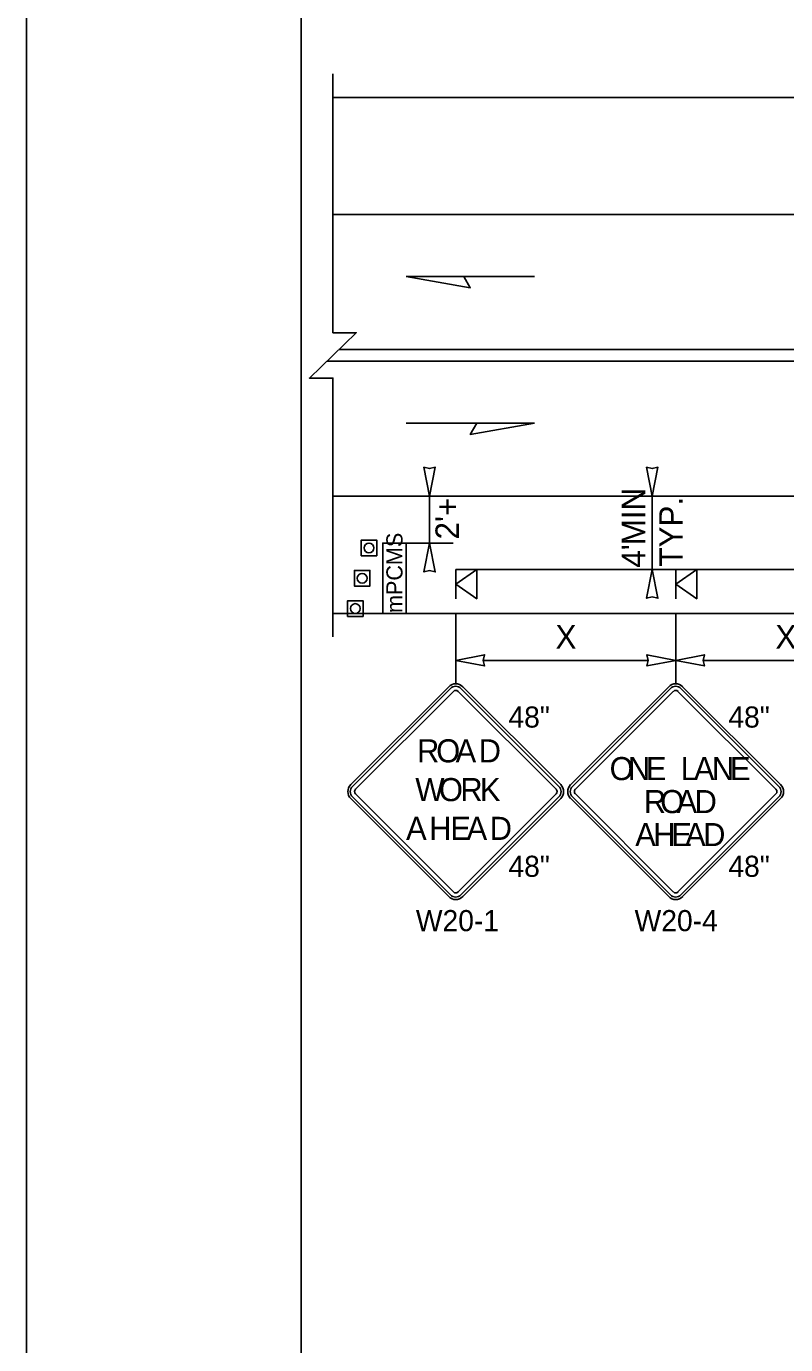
# Model space of a CAD drawing. Extents: x 99999.1 to 100095.7, y 99995 to 100010.7.
# Drawn here: x 100039.062 to 100041.652, y 100003.239 to 100007.734 of the extents above; entities that cross this region are included whole.
import ezdxf

# ---------------------------------------------------------------- set-up
doc = ezdxf.new("R2010")
doc.units = 0
for name, color, linetype in [('RD_ED_ShoulderPavedEdge', 7, 'Continuous'), ('RD_MK_LineDblYellowCenter', 7, 'Continuous'), ('RD_MK_LineEdgeWhite', 7, 'Continuous'), ('SH_GI_PlotLimits', 7, 'Continuous'), ('SH_GI_SheetBorder', 7, 'Continuous'), ('TR_SN_ConstructionSigns', 7, 'Continuous'), ('TR_WZ_PCMS', 7, 'Continuous'), ('TR_WZ_PortableSignMountBlk-Org', 7, 'Continuous'), ('TR_WZ_TrafficCone', 7, 'Continuous'), ('TR_WZ_WorkZoneDetails', 7, 'Continuous'), ('TR_WZ_WorkZoneTextCurrent', 7, 'Continuous')]:
    doc.layers.add(name, color=color, linetype=linetype)

msp = doc.modelspace()

# ---------------------------------------------------------------- linework, layer by layer
at = {"layer": 'RD_ED_ShoulderPavedEdge'}
for p, q in [((100040.1076, 100007.4923), (100055.6424, 100007.4923)), ((100040.1076, 100005.7323), (100055.6424, 100005.7323))]:
    msp.add_line(p, q, dxfattribs=at)
at = {"layer": 'RD_MK_LineDblYellowCenter'}
for p, q in [((100040.1282, 100006.6323), (100043.4767, 100006.6323)), ((100040.0869, 100006.5923), (100043.4767, 100006.5923))]:
    msp.add_line(p, q, dxfattribs=at)
at = {"layer": 'RD_MK_LineEdgeWhite'}
for p, q in [((100040.1076, 100007.0923), (100055.6424, 100007.0923)), ((100040.1076, 100006.1323), (100055.6424, 100006.1323))]:
    msp.add_line(p, q, dxfattribs=at)
at = {"layer": 'SH_GI_PlotLimits'}
msp.add_lwpolyline([(100039.0625, 99999.6875), (100056.0625, 99999.6875), (100056.0625, 100010.6875), (100039.0625, 100010.6875)], close=True, dxfattribs=at)
at = {"layer": 'SH_GI_SheetBorder'}
msp.add_line((100040, 100010.375), (100040, 100000), dxfattribs=at)
at = {"layer": 'TR_SN_ConstructionSigns'}
for p, q in [((100040.5028, 100005.4824), (100040.1687, 100005.1483)), ((100040.8846, 100005.1483), (100040.5505, 100005.4824)), ((100041.2528, 100005.4824), (100040.9187, 100005.1483)), ((100041.6346, 100005.1483), (100041.3005, 100005.4824)), ((100040.5088, 100005.4765), (100040.1746, 100005.1424)), ((100040.1846, 100005.1324), (100040.5187, 100005.4665)), ((100040.5346, 100005.4665), (100040.8687, 100005.1324)), ((100040.8787, 100005.1424), (100040.5445, 100005.4765)), ((100041.2588, 100005.4765), (100040.9246, 100005.1424)), ((100040.9346, 100005.1324), (100041.2687, 100005.4665)), ((100041.2846, 100005.4665), (100041.6187, 100005.1324)), ((100041.6287, 100005.1424), (100041.2945, 100005.4765)), ((100040.1687, 100005.1006), (100040.5028, 100004.7665)), ((100040.1746, 100005.1066), (100040.5088, 100004.7725)), ((100040.5187, 100004.7824), (100040.1846, 100005.1165)), ((100040.8687, 100005.1165), (100040.5346, 100004.7824)), ((100040.5445, 100004.7725), (100040.8787, 100005.1066)), ((100040.5505, 100004.7665), (100040.8846, 100005.1006)), ((100040.9187, 100005.1006), (100041.2528, 100004.7665)), ((100040.9246, 100005.1066), (100041.2588, 100004.7725)), ((100041.2687, 100004.7824), (100040.9346, 100005.1165)), ((100041.6187, 100005.1165), (100041.2846, 100004.7824)), ((100041.2945, 100004.7725), (100041.6287, 100005.1066)), ((100041.3005, 100004.7665), (100041.6346, 100005.1006))]:
    msp.add_line(p, q, dxfattribs=at)
for centre, radius, start, end in [((100040.5267, 100005.4586), 0.0338, 45, 135), ((100040.5267, 100005.4586), 0.0253, 45, 135), ((100041.2767, 100005.4586), 0.0338, 45, 135), ((100041.2767, 100005.4586), 0.0253, 45, 135), ((100040.5267, 100005.4586), 0.0113, 45, 135), ((100041.2767, 100005.4586), 0.0113, 45, 135), ((100040.1925, 100005.1245), 0.0338, 135, 225), ((100040.1925, 100005.1245), 0.0253, 135, 225), ((100040.1925, 100005.1245), 0.0113, 135, 225), ((100040.8608, 100005.1245), 0.0113, 315, 45), ((100040.8608, 100005.1245), 0.0253, 315, 45), ((100040.8608, 100005.1245), 0.0338, 315, 45), ((100040.9425, 100005.1245), 0.0338, 135, 225), ((100040.9425, 100005.1245), 0.0253, 135, 225), ((100040.9425, 100005.1245), 0.0113, 135, 225), ((100041.6108, 100005.1245), 0.0113, 315, 45), ((100041.6108, 100005.1245), 0.0253, 315, 45), ((100041.6108, 100005.1245), 0.0338, 315, 45), ((100040.5267, 100004.7904), 0.0338, 225, 315), ((100040.5267, 100004.7904), 0.0253, 225, 315), ((100040.5267, 100004.7904), 0.0113, 225, 315), ((100041.2767, 100004.7904), 0.0338, 225, 315), ((100041.2767, 100004.7904), 0.0253, 225, 315), ((100041.2767, 100004.7904), 0.0113, 225, 315)]:
    msp.add_arc(centre, radius, start, end, dxfattribs=at)
at = {"layer": 'TR_WZ_PCMS'}
msp.add_lwpolyline([(100040.3576, 100005.7323), (100040.3576, 100005.9723), (100040.2776, 100005.9723), (100040.2776, 100005.7323)], close=True, dxfattribs=at)
msp.add_lwpolyline([(100040.3576, 100005.7323), (100040.3576, 100005.9723), (100040.2776, 100005.9723), (100040.2776, 100005.7323), (100040.3576, 100005.7323)], dxfattribs=at)
at = {"layer": 'TR_WZ_PortableSignMountBlk-Org'}
for p, q in [((100040.5267, 100005.7824), (100040.5267, 100005.8824)), ((100041.2767, 100005.7824), (100041.2767, 100005.8824))]:
    msp.add_line(p, q, dxfattribs=at)
for points in [[(100040.5267, 100005.8323), (100040.5985, 100005.8824), (100040.5985, 100005.7824)], [(100041.2767, 100005.8323), (100041.3485, 100005.8824), (100041.3485, 100005.7824)]]:
    msp.add_lwpolyline(points, close=True, dxfattribs=at)
at = {"layer": 'TR_WZ_TrafficCone'}
for points in [[(100040.2042, 100005.9823), (100040.2576, 100005.9823), (100040.2576, 100005.929), (100040.2042, 100005.929), (100040.2042, 100005.9823)], [(100040.2042, 100005.929), (100040.2576, 100005.929), (100040.2576, 100005.9823), (100040.2042, 100005.9823), (100040.2042, 100005.929)], [(100040.1809, 100005.879), (100040.2342, 100005.879), (100040.2342, 100005.8257), (100040.1809, 100005.8257), (100040.1809, 100005.879)], [(100040.1809, 100005.8257), (100040.2342, 100005.8257), (100040.2342, 100005.879), (100040.1809, 100005.879), (100040.1809, 100005.8257)], [(100040.1576, 100005.7757), (100040.2109, 100005.7757), (100040.2109, 100005.7223), (100040.1576, 100005.7223), (100040.1576, 100005.7757)], [(100040.1576, 100005.7223), (100040.2109, 100005.7223), (100040.2109, 100005.7757), (100040.1576, 100005.7757), (100040.1576, 100005.7223)]]:
    msp.add_lwpolyline(points, dxfattribs=at)
for centre in [(100040.2309, 100005.9557), (100040.2076, 100005.8523), (100040.1842, 100005.749)]:
    msp.add_circle(centre, 0.0167, dxfattribs=at)
at = {"layer": 'TR_WZ_WorkZoneDetails'}
for p, q in [((100040.5541, 100006.8816), (100040.7952, 100006.8816)), ((100040.5987, 100006.3816), (100040.3576, 100006.3816)), ((100040.3576, 100006.1323), (100040.5176, 100006.1323)), ((100040.4376, 100006.1323), (100040.4376, 100005.9723)), ((100041.1167, 100006.1323), (100041.2767, 100006.1323)), ((100041.1967, 100005.8824), (100041.1967, 100006.1323)), ((100040.3576, 100005.9723), (100040.5176, 100005.9723)), ((100040.5267, 100005.8824), (100043.5267, 100005.8824)), ((100041.1167, 100005.8824), (100041.2767, 100005.8824)), ((100040.5267, 100005.7326), (100040.5267, 100005.4923)), ((100041.2767, 100005.7323), (100041.2767, 100005.4923)), ((100041.1829, 100005.5723), (100040.6204, 100005.5723)), ((100041.9329, 100005.5723), (100041.3704, 100005.5723))]:
    msp.add_line(p, q, dxfattribs=at)
msp.add_lwpolyline([(100040.1076, 100005.6523), (100040.1076, 100006.5349), (100040.0275, 100006.5349), (100040.1876, 100006.6898), (100040.1076, 100006.6898), (100040.1076, 100007.5723)], dxfattribs=at)
for points in [[(100040.3576, 100006.8816), (100040.5764, 100006.843), (100040.5541, 100006.8816)], [(100040.7952, 100006.3816), (100040.5764, 100006.343), (100040.5987, 100006.3816)], [(100040.4376, 100006.1323), (100040.4183, 100006.2306), (100040.4376, 100006.2261), (100040.4568, 100006.2306)], [(100041.1967, 100006.1323), (100041.1774, 100006.2306), (100041.1967, 100006.2261), (100041.2159, 100006.2306)], [(100040.4376, 100005.9723), (100040.4183, 100005.8741), (100040.4376, 100005.8786), (100040.4568, 100005.8741)], [(100041.1967, 100005.8824), (100041.1774, 100005.7841), (100041.1967, 100005.7887), (100041.2159, 100005.7841)], [(100040.5267, 100005.5723), (100040.6249, 100005.5916), (100040.6204, 100005.5723), (100040.6249, 100005.5531)], [(100041.2767, 100005.5723), (100041.1784, 100005.5916), (100041.1829, 100005.5723), (100041.1784, 100005.5531)], [(100041.2767, 100005.5723), (100041.3749, 100005.5916), (100041.3704, 100005.5723), (100041.3749, 100005.5531)]]:
    msp.add_lwpolyline(points, close=True, dxfattribs=at)

# ---------------------------------------------------------------- texts
at = {"layer": 'TR_SN_ConstructionSigns'}
for s, p in [('48"', (100040.7064, 100005.343)), ('48"', (100041.4564, 100005.343)), ('48"', (100040.7064, 100004.8339)), ('48"', (100041.4564, 100004.8339)), ('W20-1', (100040.3908, 100004.6486)), ('W20-4', (100041.1367, 100004.6486))]:
    msp.add_text(s, height=0.072, rotation=360, dxfattribs=at).set_placement(p)
for s, height, p in [('R', 0.0788, (100040.3947, 100005.2243)), ('O', 0.0788, (100040.4601, 100005.2243)), ('A', 0.0788, (100040.5263, 100005.2243)), ('D', 0.0788, (100040.605, 100005.2243)), ('O', 0.0787, (100041.0514, 100005.1638)), ('N', 0.0787, (100041.1136, 100005.1638)), ('E', 0.0787, (100041.1751, 100005.1638)), ('L', 0.0787, (100041.294, 100005.1638)), ('A', 0.0787, (100041.3389, 100005.1638)), ('N', 0.0787, (100041.4003, 100005.1638)), ('E', 0.0787, (100041.4617, 100005.1638)), ('W', 0.0788, (100040.3888, 100005.0921)), ('O', 0.0788, (100040.4692, 100005.0921)), ('R', 0.0788, (100040.5424, 100005.0921)), ('K', 0.0788, (100040.6093, 100005.0921)), ('R', 0.0787, (100041.168, 100005.0513)), ('O', 0.0787, (100041.2239, 100005.0513)), ('A', 0.0787, (100041.2798, 100005.0513)), ('D', 0.0787, (100041.3412, 100005.0513)), ('A', 0.0788, (100040.3573, 100004.9599)), ('H', 0.0788, (100040.4361, 100004.9599)), ('E', 0.0788, (100040.5085, 100004.9599)), ('A', 0.0788, (100040.5637, 100004.9599)), ('D', 0.0788, (100040.6424, 100004.9599)), ('A', 0.0787, (100041.1388, 100004.9388)), ('H', 0.0787, (100041.2003, 100004.9388)), ('E', 0.0787, (100041.2617, 100004.9388)), ('A', 0.0787, (100041.3089, 100004.9388)), ('D', 0.0787, (100041.3704, 100004.9388))]:
    msp.add_text(s, height=height, dxfattribs=at).set_placement(p)
at = {"layer": 'TR_WZ_PCMS'}
msp.add_text('mPCMS', height=0.055, rotation=90, dxfattribs=at).set_placement((100040.3451, 100005.7338))
at = {"layer": 'TR_WZ_WorkZoneTextCurrent'}
for s, rotation, p in [("2'+", 90, (100040.5376, 100005.9846)), ('MIN', 90, (100041.1727, 100005.9648)), ('TYP.', 90, (100041.3007, 100005.892)), ("4'", 90, (100041.1727, 100005.8883)), ('X', 360, (100040.8669, 100005.6123)), ('X', 360, (100041.6169, 100005.6123))]:
    msp.add_text(s, height=0.08, rotation=rotation, dxfattribs=at).set_placement(p)

doc.saveas('drawing.dxf')
